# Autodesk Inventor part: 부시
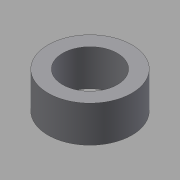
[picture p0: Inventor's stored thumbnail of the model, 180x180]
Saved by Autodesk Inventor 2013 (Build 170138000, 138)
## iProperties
Created: 2015-09
Part Number: 부시
Document SubType Name: Modeling
Designer: mduedu
Density: 1 g/cm^3
Material: 스테인리스강
Author: mduedu
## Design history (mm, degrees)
node "작업 평면1"
node "작업 평면2"
sketch "스케치1"
  geometry: C1 r 7.5 at (0, 0); C2 r 11.5 at (0, 0); 1 further point
  constraints: 2 centre point, 2 coincident
  dimensions: "d0" = 15 diameter of C1; "d1" = 23 diameter of C2
extrude "돌출1" new body sketch "스케치1" stored distance "d2" = 9.85; taper "d3" = 0 deg
node "솔리드1"
